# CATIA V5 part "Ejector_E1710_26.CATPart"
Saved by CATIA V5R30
Part number: Vyhazovac_7x160_3
Nomenclature: E1710/7x160
Description: MEUSBURGER
Property "Material": "1.221"
Publications: "__DrillHole", "Base"
Bounding box of the stored display mesh (mm): x -5.992 to 5.992, y -5.992 to 5.992, z 0 to 152
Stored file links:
  E:\Bakalarka\Model\Forma_v7\Ejector_E1710_26.CATPart
  E:\dev\MoldDesign\intel_a\startup\components\MoldCatalog\Ejector\Meusburger\Ejector_E1710\TableE1710.txt
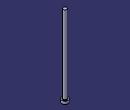
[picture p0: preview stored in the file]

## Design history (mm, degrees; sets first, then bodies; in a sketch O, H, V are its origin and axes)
Parameters
  Ref = "E1710/7x160" {design table}
  D1 = 7 mm {design table}
  D3 = 12 mm {design table}
  L = 160 mm {design table}
  L3 = 5 mm {design table}
  R = 0.5 mm {design table}
  k_d3 = 13 mm {design table}
  k_d1 = 7.2 mm {design table}
  k_F = 0.5 mm {design table}
  kl = 17 mm {design table}
  Mat = "1.221" {design table}
  HeatTreat = "ISO6751" {design table}
  Offset_Parting = 10 mm
  Anti_Rotation = "Normal"
  Anti_Rotation_D = 4 mm
  Anti_Rotation_D_Icut = 4 mm
  Add_Length_L = 1.3377 mm
  Add_Length_D3 = 0 mm
  SupplierRef = "Meusburger 2017"
  BmpRef = "F_MldEjectorD1"
  DrillHole_Length = 225 mm
  ValidationTest = false
  Anti_Rotation_D_min = 4 mm {= OffSet_D1 /2}
  Anti_Rotation_D_max = 5.925 mm {= D3/2-0.075mm}
  Anti_Rotation_D_ref = 4 mm {= Anti_Rotation_D}
  Anti_Rotation_D_Icut_ref = 4 mm {= Anti_Rotation_D_Icut}
  Anti_Rotation_Ref_Icut = 2.3246 mm
  Offset_L = 20 mm
  D = 7 mm {= D1}
  OffSet_D1 = 8 mm {= D1+2*R}
  OffSet_D3 = 13 mm {= D3+1mm}
  XG_Split = -85 mm
  YG_Split = 44.5 mm
  ZG_Split = -198 mm
  DirX_Split = 0 mm
  DirY_Split = 0 mm
  DirZ_Split = 1 mm
Set1 "BaseBody"
  Point1 "Base": (0, 0, 0)
  Plane1: type Offset, RefPlane xy-plane, Offset 225 {= DrillHole_Length}, reversed
  Sketch1 "Sketch.2" on xy-plane, origin (0, 0, 0), H (1, 0, 0), V (0, 1, 0)
    point P1 (-0.46, 1.1623)
    point P2 (0.46, 1.1623)
    construction line L1 (-0.46, 1.1623) -> (0.46, 1.1623)
    point P3 (0.46, -1.1623)
    line L2 (0.46, -1.1623) -> (0.46, 1.1623)
    point P4 (-0.46, -1.1623)
    construction line L3 (0.46, -1.1623) -> (-0.46, -1.1623)
    line L4 (-0.46, 1.1623) -> (-0.46, -1.1623)
    point P5 (-0.21, 1.1623)
    arc A1 centre (-0.21, 1.1623) radius 0.25 from (-0.21, 1.4123) to (-0.46, 1.1623) ccw
    point P7 (0.21, 1.1623)
    point P8 (0.21, 1.4123)
    arc A2 centre (0.21, 1.1623) radius 0.25 from (0.46, 1.1623) to (0.21, 1.4123) ccw
    line L5 (-0.21, 1.4123) -> (0.21, 1.4123)
    point P9 (-0.46, -1.1623)
    arc A3 centre (-0.21, -1.1623) radius 0.25 from (-0.46, -1.1623) to (-0.21, -1.4123) ccw
    point P11 (0.21, -1.4123)
    line L6 (-0.21, -1.4123) -> (0.21, -1.4123)
    point P12 (0.46, -1.1623)
    arc A4 centre (0.21, -1.1623) radius 0.25 from (0.21, -1.4123) to (0.46, -1.1623) ccw
    point P14 (-0.46, 1.1623)
    point P15 (-0.46, -1.1623)
    point P16 (0.46, 1.1623)
    point P17 (0.46, -1.1623)
    reference projected circle E1 centre (0, 0) radius 1.25 from edge [face of Shaft1 from Sketch2.L3 | face of Shaft1 from Sketch2.L4]
    reference projected circle E2 centre (0, 0) radius 1.25 from edge [face of Shaft1 from Sketch2.L3 | face of Shaft1 from Sketch2.L4]
    reference projected circle E3 centre (0, 0) radius 1.25 from edge [face of Shaft1 from Sketch2.L3 | face of Shaft1 from Sketch2.L4]
    reference projected circle E4 centre (0, 0) radius 1.25 from edge [face of Shaft1 from Sketch2.L3 | face of Shaft1 from Sketch2.L4]
    point P18 (-0.46, -1.1623)
    point P19 (-0.21, -1.4123)
    point P20 (0.21, -1.4123)
    point P21 (0.46, -1.1623)
    point P22 (-0.21, -1.4123)
    point P23 (0.21, -1.4123)
    distance P14 P15 = 2.3246 (reference)
    distance P16 P17 = 2.3246 (reference)
    distance L1 P14 = 0 (reference)
    radius A1 = 3.5
    distance L4 V = 4.01
    distance L2 V = 5.935
    distance L5 L6 = 12
    horizontal: L1 H, L3 H, L5 H
    vertical: L2 V, L4 V
    coincidence: P5 L1, P7 L1, P3 P12, P14 L4, P15 L4, P16 L2, P17 L2, P14 E1, P15 E2, P16 E3, P17 E4, P3 P21, P4 P18, P20 P23, P19 P22
    tangency: A1 L4, A2 L2, A2 L5, A1 L5
    symmetry: P1 P9 H, A1 A3 H, P8 P11 H, L5 L6 H, P2 P12 H, A2 A4 H
  DatumSurface1
Body1 "PartBody" (main body)
  Sketch2 "Sketch.1" on zx-plane, origin (0, 0, 0), H (-1, 0, 0), V (0, 0, 1)
    point P1 (0, 160)
    line L1 (3.5, 160) -> (0, 160)
    line L2 (3.5, 5) -> (3.5, 160)
    line L3 (6, 5) -> (3.5, 5)
    line L4 (6, 0) -> (6, 5)
    point P5 (0, 0)
    line L5 (0, 0) -> (6, 0)
    point P6 (0, 160)
    axis line L6 (0, 160) -> (0, 0)
    point P7 (0, 0)
    point P8 (3.5, 5)
    point P9 (3.5, 5)
    line L7 (0, 160) -> (0, 0)
    distance L5 L3 = 5 {= L3}
    distance L5 L1 = 160 {= L}
    distance L2 L6 = 3.5 {= D1 /2}
    distance L4 L6 = 6 {= D3 /2}
    coincidence: L6 P5, P1 L6, L5 H, L6 V, P7 O, P6 P1, P8 P9
    vertical: L2 V, L7 V
    horizontal: L1 H
  Shaft1 "Shaft.1": profile Sketch2, axis Sketch2.L6, angle 360
  Pocket1 "Pocket.1": profile Sketch1, direction (0, 0, 1), length 6, outer side, deactivated
  Pocket2 "Pocket.2": profile Sketch1, direction (0, 0, 1), length 6, outer side, deactivated
  Fillet1: radius 0.5 {= R}, on edge [face of Shaft1 from Sketch2.L2 | face of Shaft1 from Sketch2.L3]
  Pocket3: profile face of Shaft1 from Sketch2.L1, direction along face of Shaft1 from Sketch2.L1 reversed, up to face of DatumSurface1
Body2 "__DrillHole"
  Sketch3 "Sketch.3" on face of Shaft1, origin (0, 0, 0), H (1, 0, 0), V (0, -1, 0)
    point P1 (0, 0)
    reference projected point E1 (0, 0) from Point1
    coincidence: E1 P1
  Hole1 "Hole.1": placed by Sketch3, at (0, 0, 0) direction (0, 0, 1), diameter 8 {= OffSet_D1}, depth 140 {= L-Offset_L}
  Sketch4 "Sketch.4" on face of Shaft1, origin (0, 0, 0), H (1, 0, 0), V (0, -1, 0)
    point P1 (0, 0)
    reference projected point E1 (0, 0) from Point1
    coincidence: E1 P1
  Hole2 "Hole.2": placed by Sketch4, at (0, 0, 0) direction (0, 0, 1), diameter 7 {= D1}, depth 160 {= L}
  Sketch5 "Sketch.5" on face of Shaft1 from Sketch2.L3, origin (0, 0, 5), H (1, 0, 0), V (0, 1, 0)
    point P1 (0, 0)
    reference projected point E1 (0, 0) from Point1
    coincidence: E1 P1
  Hole3 "Hole.3": placed by Sketch5, at (0, 0, 5) direction (0, 0, -1), diameter 13 {= OffSet_D3}, depth 230 {= L3 +DrillHole_Length}
  Chamfer1: length 0.5 {= k_F}, angle 45, on edge [face of Hole1 | face of Hole3]
  Body3 "__Body.1"
    Pocket4 "Pocket.3": profile Sketch1, direction (0, 0, -1), length 225, opposite side length 5, deactivated
  Assemble1: tool Body3
  Chamfer2: length 0.5 {= k_F}, angle 45, on edge [start face of Pocket4 | face of Hole1], deactivated
  Body4 "__Body.2"
    Pocket5 "Pocket.4": profile Sketch1, direction (0, 0, -1), length 225, opposite side length 5, deactivated
  Assemble2: tool Body4
  Chamfer3: length 0.5 {= k_F}, angle 45, on edge [start face of Pocket5 | face of Hole1], deactivated
Relations
  design table "TableE1710", configuration 278, drives Ref, D1, D3, L, L3, R, k_d3, k_d1, k_F, kl, Mat, HeatTreat
  Offset_L = 20mm (deactivated)
  rule "Cut_Head_rule":
    let sketch_cut (length)
    let PartBody_Pocket_Sketch (Boolean)
    let I_PartBody_Pocket (Boolean)
    let D_PartBody_Pocket (Boolean)
    let N_DrillHole_Hole (Boolean)
    let N_DrillHole_Hole_Sketch (Boolean)
    let I_DrillHole_Pocket (Boolean)
    let D_DrillHole_Pocket (Boolean)
    /* --------------------------------------------------------------------------------------*/
    if Anti_Rotation =="Normal"
    {
    	sketch_cut=Anti_Rotation_D_max
    	PartBody_Pocket_Sketch = false
    	I_PartBody_Pocket = false
    	D_PartBody_Pocket = false
    	N_DrillHole_Hole = true
    	N_DrillHole_Hole_Sketch = true
    	I_DrillHole_Pocket = false
    	D_DrillHole_Pocket = false
    	Chamfer1.Activity= true
    	Chamfer2.Activity= false
    	Chamfer3.Activity= false
    }
    if Anti_Rotation == "I_Cut"
    {
    	sketch_cut=Anti_Rotation_D_Icut_ref
    	PartBody_Pocket_Sketch = true
    	I_PartBody_Pocket = true
    	D_PartBody_Pocket = false
    	N_DrillHole_Hole = false
    	N_DrillHole_Hole_Sketch = false
    	I_DrillHole_Pocket = true
    	D_DrillHole_Pocket = false
    	Chamfer1.Activity= false
    	Chamfer2.Activity= true
    	Chamfer3.Activity= false
    }
    if Anti_Rotation =="D_Cut"
    {
    	sketch_cut=Anti_Rotation_D_max
    	PartBody_Pocket_Sketch = true
    	I_PartBody_Pocket = false
    	D_PartBody_Pocket = true
    	N_DrillHole_Hole = false
    	N_DrillHole_Hole_Sketch = false
    	I_DrillHole_Pocket = false
    	D_DrillHole_Pocket = true
    	Chamfer1.Activity= false
    	Chamfer2.Activity= false
    	Chamfer3.Activity= true
    }
    /* --------------------------------------------------------------------------------------*/
    Sketch1.distance(L2 V) = sketch_cut+0.01mm
    Sketch1.distance(L4 V) =Anti_Rotation_D_ref+0.01mm
    Sketch1.radius(A1) =D/2
    Pocket4.FirstLimit.Depth = DrillHole_Length
    Pocket5.FirstLimit.Depth = DrillHole_Length
    Pocket1.FirstLimit.Depth = L3+1mm
    Pocket2.FirstLimit.Depth = L3+1mm
    Pocket4.SecondLimit.Depth = L3
    Pocket5.SecondLimit.Depth =L3
    Pocket1.Activity = I_PartBody_Pocket
    Pocket2.Activity = D_PartBody_Pocket
    Sketch1.Activity =PartBody_Pocket_Sketch
    Hole3.Activity= N_DrillHole_Hole
    Sketch5.Activity = N_DrillHole_Hole_Sketch
    Pocket4.Activity = I_DrillHole_Pocket
    Pocket5.Activity  = D_DrillHole_Pocket
  rule "Anti_Rotation_Icut_constrain":
    let Ref1(length)
    let Ref2(length)
    let Ref3(length)
    let Diam1(length)
    let Diam2(length)
    let Add_Length_Lmin (length)
    Ref1=Sketch1.distance(P14 P15)
    Ref2=Sketch1.distance(P16 P17)
    Diam1=D
    Diam2=D3
    /* --------------------------------------------------------------------*/
    if Ref1 >Ref2
    	Anti_Rotation_Ref_Icut = Ref1
    else
    	Anti_Rotation_Ref_Icut  =Ref2
    Add_Length_D3 .InferiorRange=Anti_Rotation_Ref_Icut /2+Diam1/2 -Diam2/2
    if Add_Length_D3 .InferiorRange<0mm
    	Add_Length_D3 .InferiorRange=0mm
    if ValidationTest == "true"
    	Ref3   = 2*Add_Length_L +Anti_Rotation_Ref_Icut  +2*Diam1/2
    else
    	Ref3  =Diam2+2*Add_Length_D3
    if Ref3 <Diam2
    {
    	Ref3 =Diam2
    }
    /* --------------------------------------------------------------------*/
    Sketch1.distance(L5 L6) = Ref3
    Add_Length_L .InferiorRange=Diam2/2-Anti_Rotation_Ref_Icut/2-Diam1/2
    Add_Length_Lmin=Diam2/2-Anti_Rotation_Ref_Icut/2-Diam1/2
    if Add_Length_Lmin<0mm
    	Add_Length_L .InferiorRange=0mm
    else
    	Add_Length_L .InferiorRange=Add_Length_Lmin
